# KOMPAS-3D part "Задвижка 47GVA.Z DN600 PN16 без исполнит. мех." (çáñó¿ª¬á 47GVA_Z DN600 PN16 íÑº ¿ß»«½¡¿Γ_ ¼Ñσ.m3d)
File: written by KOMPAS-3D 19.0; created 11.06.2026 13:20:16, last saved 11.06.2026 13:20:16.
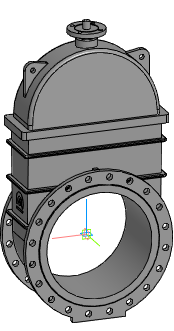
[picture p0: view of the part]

Document properties: Автор: Евгений; Полное имя файла: Z:\3.Личные\kachalov\001_3d для проектировщиков\2.2 Тип 47GVA, 47GVA.Z\_stp\_stp_Задвижка 47GVA.Z DN350-DN1200 без исп.мех\Задвижка 47GVA_Z DN600 PN16 без исполнит_ мех.m3d

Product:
- Part/product: Задвижка 47GVA.Z DN600 PN16 без исполнит. мех.

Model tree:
1. Операция без истории:1  (labels: Задвижка 47GVA.Z DN600 PN16 без исполнит. мех.)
